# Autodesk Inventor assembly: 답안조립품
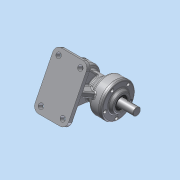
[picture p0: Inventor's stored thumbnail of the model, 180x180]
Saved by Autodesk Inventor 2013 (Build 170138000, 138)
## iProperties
Created: 2015-08
Part Number: 답안조립품
Document SubType Name: Assembly
Designer: Administrator
Author: Administrator
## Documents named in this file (10)
- C:\Users\Administrator\Desktop\450806V1009\답안조립품.iam
- C:\Users\Administrator\Desktop\450806V1009\M4x0.5.ipt
- C:\Users\Administrator\Desktop\450806V1009\뒤커버.ipt
- C:\Users\Administrator\Desktop\450806V1009\베어링 6203.ipt
- C:\Users\Administrator\Desktop\450806V1009\베어링 6205.ipt
- C:\Users\Administrator\Desktop\450806V1009\본체.ipt
- C:\Users\Administrator\Desktop\450806V1009\앞커버.ipt
- C:\Users\Administrator\Desktop\450806V1009\오일실 .ipt
- 오일실 .ipt
- C:\Users\Administrator\Desktop\450806V1009\축.ipt
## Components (2 placed, 1 different names)
1. M4x0.5:2
2. M4x0.5:1
